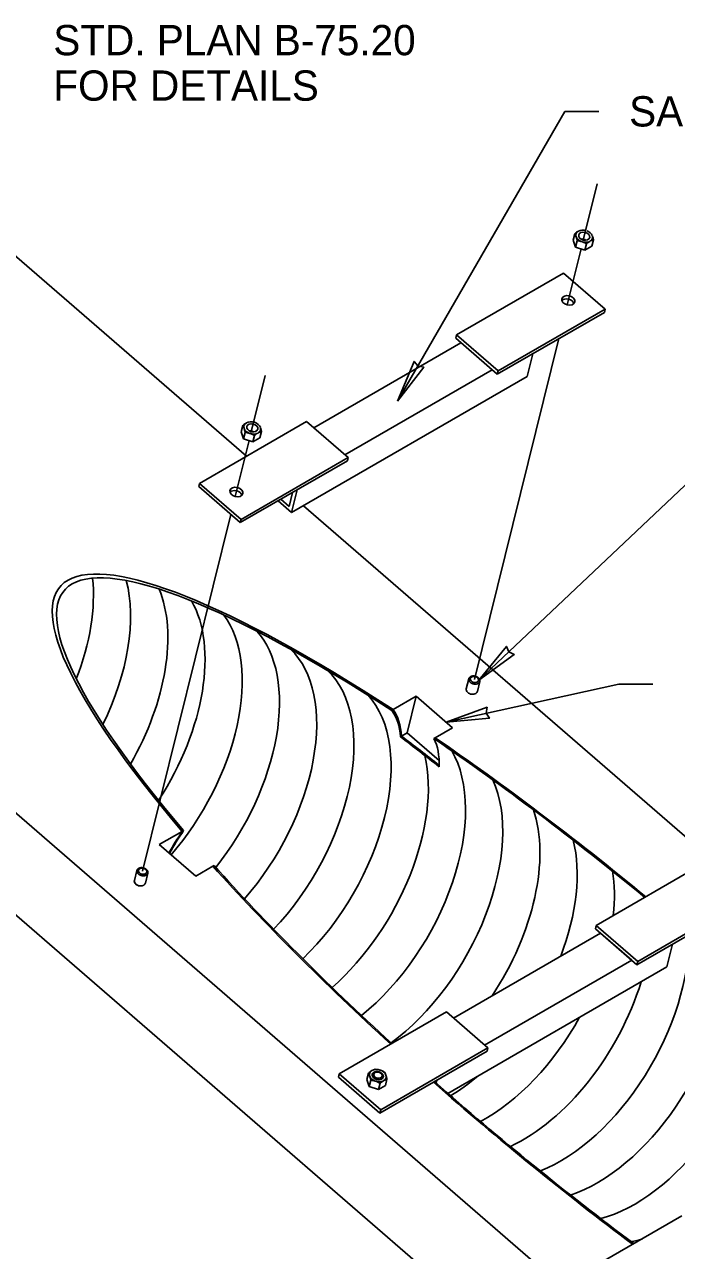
# Model space of a CAD drawing. Extents: x 99862 to 103151, y 100000 to 102076.
# Drawn here: x 101841 to 102185, y 100418 to 101065 of the extents above; entities that cross this region are included whole.
import ezdxf

# ---------------------------------------------------------------- set-up
doc = ezdxf.new("R2010")
doc.units = 0
for name, color, linetype in [('Level 1', 7, 'Continuous'), ('Level 15', 7, 'Continuous'), ('Level 20', 7, 'Continuous'), ('Level 30', 7, 'Continuous'), ('Level 62', 7, 'Continuous'), ('Level 9', 7, 'Continuous')]:
    doc.layers.add(name, color=color, linetype=linetype)

msp = doc.modelspace()

# ---------------------------------------------------------------- linework, layer by layer
at = {"layer": 'Level 1'}
for p, q in [((101757.42, 101010.8), (101958.15, 100836.96)), ((102069.17, 100901.06), (102125.73, 100933.72)), ((102147.69, 100914.71), (102125.73, 100933.72)), ((102090.69, 100880.32), (102147.26, 100912.98)), ((102091.12, 100882.05), (102147.69, 100914.71)), ((102147.26, 100912.98), (102147.69, 100914.71)), ((102071.48, 100896.95), (101993.74, 100852.07)), ((102069.17, 100901.06), (102068.74, 100899.33)), ((102068.74, 100899.33), (102090.69, 100880.32)), ((102091.12, 100882.05), (102069.17, 100901.06)), ((101553.78, 100893.22), (102304.36, 100243.2)), ((102109.43, 100891.14), (102106.46, 100879.12)), ((102106.46, 100879.12), (101982, 100807.27)), ((102087.94, 100882.69), (102010.21, 100837.81)), ((102090.69, 100880.32), (102091.12, 100882.05)), ((101989.97, 100855.34), (101933.4, 100822.68)), ((102011.92, 100836.33), (101989.97, 100855.34)), ((102259.1, 100228.52), (101542.8, 100848.86)), ((102011.49, 100834.59), (101954.92, 100801.93)), ((102011.92, 100836.33), (101955.35, 100803.67)), ((102011.49, 100834.59), (102011.92, 100836.33)), ((101933.4, 100822.68), (101932.97, 100820.94)), ((101932.97, 100820.94), (101954.92, 100801.93)), ((101955.35, 100803.67), (101933.4, 100822.68)), ((101984.98, 100819.28), (101982, 100807.27)), ((101982, 100807.27), (101974.87, 100813.45)), ((101980.72, 100810.49), (101976.33, 100814.29)), ((101982.55, 100817.88), (101980.72, 100810.49)), ((101988.26, 100810.88), (102508.01, 100360.77)), ((101954.92, 100801.93), (101955.35, 100803.67)), ((102047.9, 100710.25), (102035.62, 100703.15)), ((102047.9, 100710.25), (102043.07, 100690.86)), ((102067.1, 100693.61), (102047.9, 100710.25)), ((102034.93, 100702.75), (102035.62, 100703.15)), ((102039.52, 100688.86), (102040.11, 100689.2)), ((102043.07, 100690.86), (102040.11, 100689.2)), ((102043.07, 100690.86), (102059.98, 100676.22)), ((102067.11, 100693.61), (102057.88, 100688.28)), ((102057.88, 100688.28), (102057.23, 100687.9)), ((101912.14, 100631.86), (101924.26, 100638.86)), ((101924.26, 100638.86), (101924.95, 100639.26)), ((101931.35, 100615.22), (101912.14, 100631.86)), ((101931.35, 100615.22), (101940.4, 100620.45)), ((101941.06, 100620.83), (101940.4, 100620.45)), ((102142.97, 100589.19), (102199.54, 100621.85)), ((102164.5, 100568.45), (102221.06, 100601.11)), ((102164.93, 100570.18), (102221.49, 100602.84)), ((102142.97, 100589.19), (102142.54, 100587.46)), ((102142.54, 100587.46), (102164.5, 100568.45)), ((102164.93, 100570.18), (102142.97, 100589.19)), ((102145.29, 100585.08), (102067.55, 100540.2)), ((102145.29, 100585.08), (102161.75, 100570.82)), ((102183.24, 100579.27), (102180.26, 100567.25)), ((102180.26, 100567.25), (102064.6, 100500.47)), ((102161.75, 100570.82), (102084.02, 100525.94)), ((102164.5, 100568.45), (102164.93, 100570.18)), ((102063.78, 100543.47), (102007.21, 100510.81)), ((102085.73, 100524.46), (102063.78, 100543.47)), ((102085.3, 100522.72), (102028.73, 100490.06)), ((102085.73, 100524.46), (102029.16, 100491.8)), ((102085.3, 100522.72), (102085.73, 100524.46)), ((102007.21, 100510.81), (102006.78, 100509.07)), ((102028.73, 100490.06), (102006.78, 100509.07)), ((102029.16, 100491.8), (102007.21, 100510.81)), ((102028.73, 100490.06), (102057.07, 100506.42)), ((102058.79, 100507.41), (102058.41, 100505.89)), ((102028.73, 100490.06), (102029.16, 100491.8)), ((102188.14, 100435.77), (102131.57, 100403.11))]:
    msp.add_line(p, q, dxfattribs=at)
for centre in [(102128.22, 100919.32), (101952.86, 100818.07)]:
    msp.add_ellipse(centre, major_axis=(-3.4, 0.84), ratio=0.700141, dxfattribs=at)
for centre, major_axis, ratio, start_param, end_param in [((102127.8, 100917.58), (3.4, -0.84), 0.700141, 0.37279, 2.768803), ((101952.43, 100816.34), (3.4, -0.84), 0.700141, 0.37279, 2.768803), ((102135.04, 100536.62), (275.44, -231.36), 0.205372, 2.105302, 4.028895), ((102135.04, 100536.62), (273.14, -229.43), 0.205372, 2.111175, 4.023022), ((102077.25, 100713.41), (2.91, -0.72), 0.700141, 3.141657, 4.883928), ((102077.25, 100713.41), (2.91, -0.72), 0.700141, 4.883928, 6.427862), ((101970.23, 100631.77), (61.99, 73.83), 0.422246, 5.869517, 6.187105), ((101970.23, 100631.77), (62.51, 74.45), 0.422246, 5.866965, 6.181233), ((102054.03, 100583.39), (275.82, -231.58), 0.205105, 1.719927, 1.791084), ((102054.03, 100583.39), (273.53, -229.65), 0.205105, 1.719797, 1.793636), ((102135.04, 100536.62), (273.14, -229.43), 0.205372, 1.620244, 2.026176), ((101990.64, 100619.99), (61.99, 73.83), 0.422246, 5.795678, 6.102106), ((102135.04, 100536.62), (275.44, -231.36), 0.205372, 1.619206, 2.021302), ((101970.23, 100631.77), (61.99, 73.83), 0.422246, 1.815767, 1.969134), ((102135.04, 100536.62), (275.44, -231.36), 0.205372, 4.112895, 4.514991), ((102135.04, 100536.62), (273.14, -229.43), 0.205372, 4.108021, 4.513953), ((101901.88, 100612.16), (2.91, -0.72), 0.700141, 3.099861, 4.883928), ((101901.88, 100612.16), (2.91, -0.72), 0.700141, 4.883928, 6.407408), ((102135.04, 100536.62), (275.44, -231.36), 0.205372, 4.600023, 4.980477), ((102135.04, 100536.62), (273.14, -229.43), 0.205372, 4.599705, 4.983475), ((102182.97, 100508.95), (-48, -83.14), 0.57735, 0.462018, 0.553021)]:
    msp.add_ellipse(centre, major_axis=major_axis, ratio=ratio, start_param=start_param, end_param=end_param, dxfattribs=at)
msp.add_open_spline([(101917.17, 100627.5), (101919.36, 100631.3), (101921.73, 100635.09), (101924.26, 100638.86)], degree=3, dxfattribs=at)
at = {"layer": 'Level 15'}
for p, q in [((102037.97, 100866.02), (102126.38, 101019.16)), ((102126.38, 101019.16), (102144.36, 101019.16)), ((102143.46, 100980.87), (102136.11, 100951.18)), ((102134.96, 100946.5), (102127.64, 100916.94)), ((102123.22, 100899.1), (102078.65, 100719.07)), ((101968.1, 100879.62), (101960.75, 100849.93)), ((101959.59, 100845.26), (101952.27, 100815.69)), ((102081.01, 100718.73), (102193.03, 100824.54)), ((101949.93, 100806.25), (101903.28, 100617.82)), ((102063.63, 100696.62), (102154.98, 100716.62)), ((102154.98, 100716.62), (102172.96, 100716.62))]:
    msp.add_line(p, q, dxfattribs=at)
for points in [[(102037.97, 100866.02), (102046.73, 100887.06), (102048.76, 100884.68), (102051.84, 100884.1)], [(102081.01, 100718.73), (102099.66, 100732.24), (102096.84, 100733.68), (102095.56, 100736.58)], [(102063.63, 100696.62), (102086.57, 100698.59), (102084.9, 100701.28), (102085.29, 100704.42)]]:
    msp.add_lwpolyline(points, close=True, dxfattribs=at)
at = {"layer": 'Level 30'}
for centre, start_param, end_param in [((101809.46, 100724.6), 1.833627, 2.472718), ((101829.11, 100713.25), 1.686533, 2.617527), ((101848.77, 100701.9), 1.573634, 2.727204), ((101868.43, 100690.55), 1.481091, 2.818494), ((101888.09, 100679.2), 1.247257, 2.896434), ((101907.75, 100667.85), 1.313092, 2.96082), ((101927.41, 100656.5), 1.239616, 3.004202), ((101947.07, 100645.15), 1.170092, 3.007636), ((101966.73, 100633.8), 1.103655, 2.964321), ((101986.38, 100622.45), 1.039675, 2.593262), ((102006.04, 100611.1), 0.977667, 2.824258), ((102025.7, 100599.75), 0.917248, 2.749749), ((102045.36, 100588.4), 1.464154, 2.675681), ((102065.02, 100577.05), 1.845533, 2.60241), ((102084.68, 100565.7), 2.226151, 2.531506), ((102123.99, 100543), 0.629638, 2.382546), ((102143.65, 100531.65), 0.573632, 2.314378), ((102104.34, 100554.35), 0.68593, 1.950535), ((102163.31, 100520.3), 0.51779, 2.242249), ((102084.68, 100565.7), 0.742656, 1.602654), ((102065.02, 100577.05), 0.799984, 1.0147)]:
    msp.add_ellipse(centre, major_axis=(-48, -83.14), ratio=0.57735, start_param=start_param, end_param=end_param, dxfattribs=at)
at = {"layer": 'Level 62'}
for points in [[(102075.52, 100718.8), (102075.55, 100718.87), (102075.59, 100718.93), (102075.63, 100718.99)], [(101899, 100612.97), (101898.78, 100611.88), (101899.55, 100610.85), (101900.88, 100610.28)]]:
    msp.add_open_spline(points, degree=3, dxfattribs=at)
at = {"layer": 'Level 9'}
for p, q in [((102131.62, 100954.55), (102130.79, 100951.19)), ((102132.04, 100947.46), (102130.79, 100951.19)), ((102132.87, 100950.82), (102132.04, 100947.46)), ((102137.8, 100949.21), (102136.96, 100945.84)), ((102141.47, 100951.33), (102140.64, 100947.97)), ((102136.96, 100945.84), (102132.04, 100947.46)), ((102140.64, 100947.97), (102136.96, 100945.84)), ((101956.26, 100853.31), (101955.43, 100849.95)), ((101955.43, 100849.95), (101956.68, 100846.21)), ((101957.51, 100849.57), (101956.68, 100846.21)), ((101956.68, 100846.21), (101961.6, 100844.6)), ((101959.93, 100849.08), (101960.16, 100849.01)), ((101962.43, 100847.96), (101961.6, 100844.6)), ((101961.6, 100844.6), (101965.28, 100846.72)), ((101966.11, 100850.08), (101965.28, 100846.72)), ((102075.66, 100719.5), (102074.33, 100714.13)), ((102080.16, 100712.69), (102081.49, 100718.06)), ((101900.3, 100618.26), (101898.97, 100612.88)), ((101904.8, 100611.44), (101906.13, 100616.81)), ((102022.58, 100511.17), (102021.75, 100507.81)), ((102021.75, 100507.81), (102023, 100504.08)), ((102023.25, 100509.65), (102023.29, 100509.52)), ((102032.42, 100507.95), (102031.59, 100504.59)), ((102023.83, 100507.44), (102023, 100504.08)), ((102023, 100504.08), (102027.92, 100502.47)), ((102026.24, 100506.95), (102026.47, 100506.87)), ((102028.75, 100505.83), (102027.92, 100502.47)), ((102027.92, 100502.47), (102031.59, 100504.59)), ((102030.58, 100507.12), (102030.73, 100507.21))]:
    msp.add_line(p, q, dxfattribs=at)
for centre, major_axis, start_param, end_param in [((102136.62, 100953.22), (4.37, -1.08), 2.512579, 4.59379), ((102136.62, 100953.22), (4.37, -1.08), 1.486271, 2.512579), ((102136.62, 100953.22), (4.37, -1.08), 0.445426, 1.444492), ((102135.72, 100949.58), (2.91, -0.72), 1.102474, 2.039119), ((102136.62, 100953.22), (4.37, -1.08), 4.620204, 5.629445), ((102136.62, 100953.22), (4.37, -1.08), 5.678899, 6.674128), ((101961.25, 100851.97), (4.37, -1.08), 2.512579, 3.538887), ((101961.25, 100851.97), (4.37, -1.08), 3.580667, 4.579733), ((101961.25, 100851.97), (4.37, -1.08), 0.431368, 2.512579), ((101961.25, 100851.97), (4.37, -1.08), 5.678899, 6.68814), ((101960.35, 100848.33), (2.91, -0.72), 1.102474, 2.039119), ((101961.25, 100851.97), (4.37, -1.08), 4.634216, 5.629445), ((102027.57, 100509.84), (4.37, -1.08), 2.512579, 3.538887), ((102027.57, 100509.84), (4.37, -1.08), 3.580667, 4.579733), ((102027.57, 100509.84), (-2.91, 0.72), 5.654172, 6.714441), ((102027.57, 100509.84), (2.91, -0.72), 2.167763, 5.999016), ((102027.57, 100509.84), (4.37, -1.08), 0.431368, 2.512579), ((102027.57, 100509.84), (4.37, -1.08), 5.678899, 6.68814), ((102027.57, 100509.84), (4.37, -1.08), 4.634216, 5.629445)]:
    msp.add_ellipse(centre, major_axis=major_axis, ratio=0.700141, start_param=start_param, end_param=end_param, dxfattribs=at)
for centre, major_axis in [((102136.62, 100953.22), (-2.91, 0.72)), ((101961.25, 100851.97), (-2.91, 0.72)), ((102078.65, 100719.07), (2.21, -0.55)), ((101903.28, 100617.82), (2.21, -0.55)), ((102027.64, 100510.12), (2.21, -0.55))]:
    msp.add_ellipse(centre, major_axis=major_axis, ratio=0.700141, dxfattribs=at)
for points, degree in [([(102133.53, 100955.89), (102133.37, 100955.8), (102133.21, 100955.7), (102133.05, 100955.6), (102132.58, 100955.29), (102132.1, 100954.93), (102131.62, 100954.55)], 3), ([(102132.87, 100950.82), (102132.7, 100951.64), (102132.5, 100952.43), (102132.27, 100953.09), (102132.07, 100953.66), (102131.85, 100954.14), (102131.62, 100954.55)], 3), ([(102135.35, 100950.31), (102135.31, 100950.32), (102135.27, 100950.33), (102135.23, 100950.34), (102134.46, 100950.58), (102133.66, 100950.73), (102132.87, 100950.82)], 3), ([(102137.8, 100949.21), (102137.06, 100949.63), (102136.27, 100950), (102135.46, 100950.27)], 2), ([(102139.62, 100950.5), (102139.49, 100950.42), (102139.36, 100950.34), (102139.23, 100950.25), (102138.75, 100949.95), (102138.27, 100949.59), (102137.8, 100949.21)], 3), ([(102141.47, 100951.33), (102141.34, 100951.28), (102141.2, 100951.24), (102141.07, 100951.19), (102140.66, 100951.04), (102140.23, 100950.84), (102139.78, 100950.59)], 3), ([(102140.94, 100953.38), (102140.95, 100953.37), (102140.95, 100953.36), (102140.96, 100953.34), (102141.15, 100952.74), (102141.32, 100952.05), (102141.47, 100951.33)], 3), ([(101956.26, 100853.31), (101956.41, 100853.43), (101956.57, 100853.55), (101956.72, 100853.66), (101957.2, 100854.03), (101957.69, 100854.37), (101958.17, 100854.64)], 3), ([(101956.26, 100853.31), (101956.5, 100852.88), (101956.73, 100852.39), (101956.93, 100851.78)], 2), ([(101956.98, 100851.65), (101956.98, 100851.63), (101956.99, 100851.61), (101957, 100851.59), (101957.19, 100850.99), (101957.36, 100850.29), (101957.51, 100849.57)], 3), ([(101966.11, 100850.08), (101965.95, 100850.84), (101965.77, 100851.56), (101965.57, 100852.18)], 2), ([(101957.51, 100849.57), (101958.31, 100849.48), (101959.13, 100849.33), (101959.93, 100849.08)], 2), ([(101960.16, 100849.01), (101960.18, 100849), (101960.19, 100848.99), (101960.21, 100848.99), (101960.98, 100848.72), (101961.73, 100848.36), (101962.43, 100847.96)], 3), ([(101962.43, 100847.96), (101962.59, 100848.08), (101962.74, 100848.2), (101962.89, 100848.32), (101963.35, 100848.67), (101963.81, 100848.99), (101964.26, 100849.25)], 3), ([(101964.42, 100849.34), (101964.55, 100849.42), (101964.68, 100849.49), (101964.81, 100849.55), (101965.26, 100849.78), (101965.69, 100849.95), (101966.11, 100850.08)], 3), ([(102078.3, 100716.69), (102078.63, 100716.63), (102078.97, 100716.61), (102079.29, 100716.62), (102079.61, 100716.64), (102079.93, 100716.7), (102080.2, 100716.8), (102080.48, 100716.9), (102080.73, 100717.04), (102080.93, 100717.2), (102081.13, 100717.37), (102081.29, 100717.57), (102081.39, 100717.78), (102081.49, 100718), (102081.54, 100718.23), (102081.53, 100718.47), (102081.52, 100718.71), (102081.46, 100718.96), (102081.34, 100719.2), (102081.22, 100719.44), (102081.05, 100719.67), (102080.84, 100719.88), (102080.63, 100720.09), (102080.37, 100720.28), (102080.08, 100720.43), (102079.8, 100720.59), (102079.48, 100720.72), (102079.16, 100720.8), (102078.83, 100720.89), (102078.49, 100720.94), (102078.16, 100720.94), (102077.84, 100720.95), (102077.51, 100720.92), (102077.22, 100720.84), (102076.92, 100720.77), (102076.65, 100720.65), (102076.43, 100720.51), (102076.2, 100720.36), (102076.01, 100720.18), (102075.88, 100719.98), (102075.74, 100719.78), (102075.66, 100719.55), (102075.63, 100719.31), (102075.6, 100719.08), (102075.63, 100718.83), (102075.72, 100718.59), (102075.8, 100718.35), (102075.94, 100718.11), (102076.13, 100717.89), (102076.31, 100717.67), (102076.54, 100717.46), (102076.81, 100717.29), (102077.08, 100717.11), (102077.38, 100716.96), (102077.69, 100716.85), (102077.89, 100716.78), (102078.1, 100716.73), (102078.3, 100716.69)], 3), ([(101906.16, 100617.3), (101906.18, 100617.06), (101906.15, 100616.82), (101906.06, 100616.61), (101905.97, 100616.39), (101905.82, 100616.18), (101905.63, 100616.01), (101905.44, 100615.84), (101905.2, 100615.7), (101904.93, 100615.59), (101904.66, 100615.49), (101904.36, 100615.42), (101904.04, 100615.39), (101903.72, 100615.36), (101903.38, 100615.37), (101903.05, 100615.43), (101902.72, 100615.48), (101902.39, 100615.58), (101902.09, 100615.71), (101901.78, 100615.83), (101901.49, 100616), (101901.25, 100616.19), (101901, 100616.38), (101900.79, 100616.6), (101900.63, 100616.82), (101900.47, 100617.05), (101900.35, 100617.3), (101900.3, 100617.54), (101900.24, 100617.78), (101900.24, 100618.03), (101900.3, 100618.25), (101900.36, 100618.48), (101900.47, 100618.7), (101900.63, 100618.89), (101900.79, 100619.08), (101901, 100619.24), (101901.25, 100619.37), (101901.5, 100619.5), (101901.79, 100619.59), (101902.09, 100619.65), (101902.4, 100619.7), (101902.73, 100619.71), (101903.06, 100619.68), (101903.39, 100619.65), (101903.73, 100619.58), (101904.05, 100619.48), (101904.37, 100619.37), (101904.67, 100619.22), (101904.94, 100619.05), (101905.21, 100618.88), (101905.45, 100618.68), (101905.64, 100618.46), (101905.83, 100618.24), (101905.97, 100618), (101906.06, 100617.76), (101906.12, 100617.61), (101906.15, 100617.45), (101906.16, 100617.3)], 3), ([(102022.58, 100511.17), (102022.73, 100511.3), (102022.88, 100511.41), (102023.03, 100511.53), (102023.52, 100511.9), (102024.01, 100512.24), (102024.48, 100512.51)], 3), ([(102022.58, 100511.17), (102022.81, 100510.75), (102023.04, 100510.25), (102023.25, 100509.65)], 2), ([(102023.29, 100509.52), (102023.3, 100509.5), (102023.31, 100509.47), (102023.31, 100509.45), (102023.51, 100508.85), (102023.68, 100508.16), (102023.83, 100507.44)], 3), ([(102024.48, 100512.51), (102024.64, 100512.6), (102024.8, 100512.69), (102024.95, 100512.76), (102025.4, 100512.99), (102025.84, 100513.16), (102026.25, 100513.29)], 3), ([(102030.52, 100509.61), (102030.54, 100509.37), (102030.5, 100509.13), (102030.41, 100508.91), (102030.32, 100508.69), (102030.18, 100508.49), (102029.99, 100508.32), (102029.8, 100508.14), (102029.56, 100508), (102029.29, 100507.89), (102029.02, 100507.79), (102028.71, 100507.72), (102028.4, 100507.69), (102028.08, 100507.66), (102027.74, 100507.68), (102027.41, 100507.73), (102027.08, 100507.78), (102026.75, 100507.88), (102026.44, 100508.01), (102026.14, 100508.14), (102025.85, 100508.3), (102025.6, 100508.49), (102025.36, 100508.68), (102025.14, 100508.9), (102024.98, 100509.13), (102024.82, 100509.36), (102024.71, 100509.6), (102024.66, 100509.84), (102024.6, 100510.09), (102024.6, 100510.33), (102024.66, 100510.56), (102024.71, 100510.79), (102024.83, 100511), (102024.99, 100511.19), (102025.15, 100511.38), (102025.36, 100511.55), (102025.61, 100511.67), (102025.86, 100511.8), (102026.14, 100511.9), (102026.45, 100511.95), (102026.76, 100512), (102027.09, 100512.01), (102027.42, 100511.99), (102027.75, 100511.96), (102028.09, 100511.89), (102028.4, 100511.78), (102028.72, 100511.67), (102029.03, 100511.53), (102029.3, 100511.36), (102029.56, 100511.18), (102029.8, 100510.98), (102029.99, 100510.76), (102030.18, 100510.54), (102030.33, 100510.3), (102030.42, 100510.06), (102030.47, 100509.91), (102030.51, 100509.76), (102030.52, 100509.61)], 3), ([(102031.18, 100511.68), (102030.37, 100512.14), (102029.5, 100512.55), (102028.61, 100512.82), (102027.83, 100513.06), (102027.03, 100513.21), (102026.25, 100513.29)], 3), ([(102030.73, 100507.21), (102030.87, 100507.28), (102030.99, 100507.35), (102031.12, 100507.42), (102031.58, 100507.65), (102032.01, 100507.82), (102032.42, 100507.95)], 3), ([(102031.85, 100510.14), (102031.84, 100510.16), (102031.84, 100510.19), (102031.83, 100510.22), (102031.63, 100510.79), (102031.4, 100511.27), (102031.18, 100511.68)], 3), ([(102032.42, 100507.95), (102032.27, 100508.7), (102032.09, 100509.43), (102031.88, 100510.05)], 2), ([(102023.83, 100507.44), (102024.63, 100507.35), (102025.45, 100507.2), (102026.24, 100506.95)], 2), ([(102026.47, 100506.87), (102026.49, 100506.87), (102026.51, 100506.86), (102026.53, 100506.86), (102027.3, 100506.59), (102028.05, 100506.23), (102028.75, 100505.83)], 3), ([(102028.75, 100505.83), (102028.9, 100505.95), (102029.05, 100506.07), (102029.21, 100506.18), (102029.67, 100506.54), (102030.13, 100506.86), (102030.58, 100507.12)], 3)]:
    msp.add_open_spline(points, degree=degree, dxfattribs=at)

# ---------------------------------------------------------------- texts
at = {"layer": 'Level 20'}
for s, p in [('STD. PLAN B-75.20', (101856.13, 101048.78)), ('FOR DETAILS', (101856.13, 101024.78)), ('SAFETY BAR (TYP.)', (102160.36, 101011.16))]:
    msp.add_text(s, height=16, dxfattribs=at).set_placement(p)

doc.saveas('drawing.dxf')
